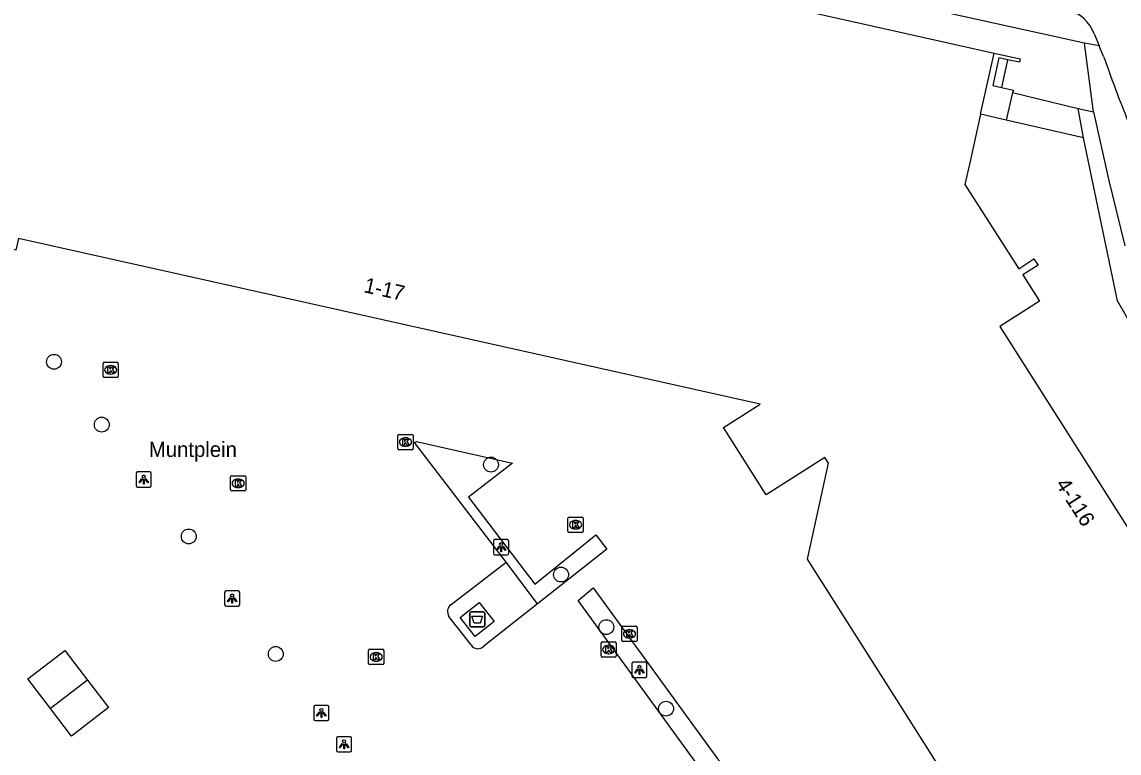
# Model space of a CAD drawing. Extents: x 161771 to 163125, y 382479 to 383177.
# Drawn here: x 162172.1 to 162244.3, y 382996.5 to 383044.7 of the extents above; entities that cross this region are included whole.
import ezdxf

# ---------------------------------------------------------------- set-up
doc = ezdxf.new("R2010")
doc.units = 0
for name, color, linetype in [('IMGEO_Afval_apart_plaats', 7, 'Continuous'), ('IMGEO_Boom', 7, 'Continuous'), ('IMGEO_Fietspad_gesloten', 7, 'Continuous'), ('IMGEO_Groenvoorziening', 7, 'Continuous'), ('IMGEO_Haag', 7, 'Continuous'), ('IMGEO_Kolk', 7, 'Continuous'), ('IMGEO_Lichtpunt', 7, 'Continuous'), ('IMGEO_Openbare_ruimte_label', 7, 'Continuous'), ('IMGEO_Pand', 7, 'Continuous'), ('IMGEO_Pand_nummerreeks', 7, 'Continuous'), ('IMGEO_Voetpad_gesloten', 7, 'Continuous'), ('IMGEO_Voetpad_open', 7, 'Continuous')]:
    doc.layers.add(name, color=color, linetype=linetype)

msp = doc.modelspace()

# ---------------------------------------------------------------- linework, layer by layer
at = {"layer": 'IMGEO_Afval_apart_plaats'}
for p, q in [((162201.588, 383004.906), (162201.588, 383005.706)), ((162201.588, 383005.706), (162201.588, 383004.906)), ((162201.688, 383005.806), (162202.478, 383005.806)), ((162202.478, 383005.806), (162201.688, 383005.806)), ((162202.578, 383005.706), (162202.578, 383004.906)), ((162202.578, 383004.906), (162202.578, 383005.706)), ((162202.478, 383004.806), (162201.688, 383004.806)), ((162201.688, 383004.806), (162202.478, 383004.806))]:
    msp.add_line(p, q, dxfattribs=at)
msp.add_lwpolyline([(162201.731, 383005.52), (162202.435, 383005.52), (162202.286, 383005.05), (162201.88, 383005.05), (162201.731, 383005.52)], dxfattribs=at)
for centre, start, end in [((162201.688, 383005.706), 90, 180), ((162201.688, 383005.706), 90, 180), ((162202.478, 383005.706), 0, 90), ((162202.478, 383005.706), 360, 90), ((162201.688, 383004.906), 180, 270), ((162201.688, 383004.906), 180, 270), ((162202.478, 383004.906), 270, 0), ((162202.478, 383004.906), 270, 0)]:
    msp.add_arc(centre, 0.1, start, end, dxfattribs=at)
at = {"layer": 'IMGEO_Boom'}
for centre in [(162174.228, 383022.27), (162177.372, 383018.135), (162202.992, 383015.501), (162183.098, 383010.768), (162207.602, 383008.259), (162210.585, 383004.797), (162188.826, 383003.033), (162214.515, 382999.426)]:
    msp.add_circle(centre, 0.489, dxfattribs=at)
at = {"layer": 'IMGEO_Fietspad_gesloten'}
for points in [[(162242.707, 383043.825), (162243.022, 383043.077)], [(162243.314, 383042.384), (162243.022, 383043.077)]]:
    msp.add_lwpolyline(points, dxfattribs=at)
for centre, radius, start, end in [((162240.222, 383042.932), 2.641, 19.77497, 74.56102), ((162333.223, 383073.685), 95.202, 199.19524, 201.97208)]:
    msp.add_arc(centre, radius, start, end, dxfattribs=at)
at = {"layer": 'IMGEO_Groenvoorziening'}
msp.add_lwpolyline([(162259.402, 382999.848), (162259.315, 383000), (162244.219, 383026.291), (162241.992, 383037.016)], dxfattribs=at)
at = {"layer": 'IMGEO_Haag'}
for points in [[(162203.991, 383009.068), (162197.95, 383016.959), (162198.094, 383017.031), (162204.406, 383015.589), (162201.521, 383013.363), (162205.876, 383007.632), (162209.901, 383010.868), (162210.617, 383009.929), (162206.053, 383006.34)], [(162231.583, 382975.071), (162208.719, 383006.559), (162209.718, 383007.386), (162232.645, 382975.85)]]:
    msp.add_lwpolyline(points, dxfattribs=at)
at = {"layer": 'IMGEO_Kolk'}
for p, q in [((162177.456, 383021.311), (162177.456, 383022.163)), ((162177.531, 383022.237), (162178.383, 383022.237)), ((162177.944, 383022.017), (162177.969, 383022.017)), ((162178.457, 383022.163), (162178.457, 383021.311)), ((162178.383, 383021.237), (162177.531, 383021.237)), ((162177.967, 383021.457), (162177.942, 383021.457)), ((162196.86, 383016.557), (162196.86, 383017.409)), ((162196.935, 383017.483), (162197.787, 383017.483)), ((162197.348, 383017.263), (162197.373, 383017.263)), ((162197.861, 383017.409), (162197.861, 383016.557)), ((162197.371, 383016.703), (162197.346, 383016.703)), ((162197.787, 383016.483), (162196.935, 383016.483)), ((162185.852, 383013.839), (162185.852, 383014.691)), ((162185.927, 383014.765), (162186.779, 383014.765)), ((162186.34, 383014.545), (162186.365, 383014.545)), ((162186.853, 383014.691), (162186.853, 383013.839)), ((162186.779, 383013.765), (162185.927, 383013.765)), ((162186.363, 383013.985), (162186.338, 383013.985)), ((162208.058, 383011.113), (162208.058, 383011.965)), ((162208.133, 383012.039), (162208.985, 383012.039)), ((162208.546, 383011.819), (162208.571, 383011.819)), ((162209.059, 383011.965), (162209.059, 383011.113)), ((162208.985, 383011.039), (162208.133, 383011.039)), ((162208.569, 383011.259), (162208.544, 383011.259)), ((162211.604, 383003.927), (162211.604, 383004.779)), ((162211.679, 383004.853), (162212.531, 383004.853)), ((162212.092, 383004.633), (162212.117, 383004.633)), ((162212.605, 383004.779), (162212.605, 383003.927)), ((162210.236, 383002.898), (162210.236, 383003.75)), ((162210.311, 383003.824), (162211.163, 383003.824)), ((162210.724, 383003.604), (162210.749, 383003.604)), ((162211.237, 383003.75), (162211.237, 383002.898)), ((162212.531, 383003.853), (162211.679, 383003.853)), ((162212.115, 383004.073), (162212.09, 383004.073)), ((162194.93, 383002.41), (162194.93, 383003.262)), ((162195.005, 383003.336), (162195.857, 383003.336)), ((162195.418, 383003.116), (162195.443, 383003.116)), ((162195.931, 383003.262), (162195.931, 383002.41)), ((162211.163, 383002.824), (162210.311, 383002.824)), ((162210.747, 383003.044), (162210.722, 383003.044)), ((162195.857, 383002.336), (162195.005, 383002.336)), ((162195.441, 383002.556), (162195.416, 383002.556))]:
    msp.add_line(p, q, dxfattribs=at)
for points in [[(162177.456, 383021.311), (162177.456, 383022.163)], [(162177.531, 383022.237), (162178.383, 383022.237)], [(162177.777, 383021.937), (162177.9, 383021.937), (162177.9, 383021.786), (162178.03, 383021.937), (162178.194, 383021.937), (162178.048, 383021.786), (162178.201, 383021.537), (162178.049, 383021.537), (162177.964, 383021.701), (162177.9, 383021.634), (162177.9, 383021.537), (162177.777, 383021.537), (162177.777, 383021.937)], [(162178.457, 383022.163), (162178.457, 383021.311)], [(162178.383, 383021.237), (162177.531, 383021.237)], [(162196.86, 383016.557), (162196.86, 383017.409)], [(162196.935, 383017.483), (162197.787, 383017.483)], [(162197.861, 383017.409), (162197.861, 383016.557)], [(162197.181, 383017.183), (162197.304, 383017.183), (162197.304, 383017.032), (162197.434, 383017.183), (162197.598, 383017.183), (162197.452, 383017.032), (162197.605, 383016.783), (162197.453, 383016.783), (162197.368, 383016.947), (162197.304, 383016.88), (162197.304, 383016.783), (162197.181, 383016.783), (162197.181, 383017.183)], [(162197.787, 383016.483), (162196.935, 383016.483)], [(162185.852, 383013.839), (162185.852, 383014.691)], [(162185.927, 383014.765), (162186.779, 383014.765)], [(162186.173, 383014.465), (162186.296, 383014.465), (162186.296, 383014.314), (162186.426, 383014.465), (162186.59, 383014.465), (162186.444, 383014.314), (162186.597, 383014.065), (162186.445, 383014.065), (162186.36, 383014.229), (162186.296, 383014.162), (162186.296, 383014.065), (162186.173, 383014.065), (162186.173, 383014.465)], [(162186.853, 383014.691), (162186.853, 383013.839)], [(162186.779, 383013.765), (162185.927, 383013.765)], [(162208.058, 383011.113), (162208.058, 383011.965)], [(162208.133, 383012.039), (162208.985, 383012.039)], [(162208.379, 383011.739), (162208.502, 383011.739), (162208.502, 383011.588), (162208.632, 383011.739), (162208.796, 383011.739), (162208.65, 383011.588), (162208.803, 383011.339), (162208.651, 383011.339), (162208.566, 383011.503), (162208.502, 383011.436), (162208.502, 383011.339), (162208.379, 383011.339), (162208.379, 383011.739)], [(162209.059, 383011.965), (162209.059, 383011.113)], [(162208.985, 383011.039), (162208.133, 383011.039)], [(162211.604, 383003.927), (162211.604, 383004.779)], [(162211.679, 383004.853), (162212.531, 383004.853)], [(162211.925, 383004.553), (162212.048, 383004.553), (162212.048, 383004.402), (162212.178, 383004.553), (162212.342, 383004.553), (162212.196, 383004.402), (162212.349, 383004.153), (162212.197, 383004.153), (162212.112, 383004.317), (162212.048, 383004.25), (162212.048, 383004.153), (162211.925, 383004.153), (162211.925, 383004.553)], [(162212.605, 383004.779), (162212.605, 383003.927)], [(162210.236, 383002.898), (162210.236, 383003.75)], [(162210.311, 383003.824), (162211.163, 383003.824)], [(162210.557, 383003.524), (162210.68, 383003.524), (162210.68, 383003.373), (162210.81, 383003.524), (162210.974, 383003.524), (162210.828, 383003.373), (162210.981, 383003.124), (162210.829, 383003.124), (162210.744, 383003.288), (162210.68, 383003.221), (162210.68, 383003.124), (162210.557, 383003.124), (162210.557, 383003.524)], [(162211.237, 383003.75), (162211.237, 383002.898)], [(162212.531, 383003.853), (162211.679, 383003.853)], [(162194.93, 383002.41), (162194.93, 383003.262)], [(162195.005, 383003.336), (162195.857, 383003.336)], [(162195.251, 383003.036), (162195.374, 383003.036), (162195.374, 383002.885), (162195.504, 383003.036), (162195.668, 383003.036), (162195.522, 383002.885), (162195.675, 383002.636), (162195.523, 383002.636), (162195.438, 383002.8), (162195.374, 383002.733), (162195.374, 383002.636), (162195.251, 383002.636), (162195.251, 383003.036)], [(162195.931, 383003.262), (162195.931, 383002.41)], [(162211.163, 383002.824), (162210.311, 383002.824)], [(162195.857, 383002.336), (162195.005, 383002.336)]]:
    msp.add_lwpolyline(points, dxfattribs=at)
for centre, start, end in [((162177.533, 383022.161), 91.55205, 178.44795), ((162177.533, 383022.161), 91.55205, 178.44795), ((162178.381, 383022.161), 1.55205, 88.44795), ((162178.381, 383022.161), 1.55205, 88.44795), ((162177.533, 383021.313), 181.55205, 268.44795), ((162177.533, 383021.313), 181.55205, 268.44795), ((162178.381, 383021.313), 271.55205, 358.44795), ((162178.381, 383021.313), 271.55205, 358.44795), ((162196.937, 383017.407), 91.55205, 178.44795), ((162196.937, 383017.407), 91.55205, 178.44795), ((162197.785, 383017.407), 1.55205, 88.44795), ((162197.785, 383017.407), 1.55205, 88.44795), ((162196.937, 383016.559), 181.55205, 268.44795), ((162196.937, 383016.559), 181.55205, 268.44795), ((162197.785, 383016.559), 271.55205, 358.44795), ((162197.785, 383016.559), 271.55205, 358.44795), ((162185.929, 383014.689), 91.55205, 178.44795), ((162185.929, 383014.689), 91.55205, 178.44795), ((162186.777, 383014.689), 1.55205, 88.44795), ((162186.777, 383014.689), 1.55205, 88.44795), ((162185.929, 383013.841), 181.55205, 268.44795), ((162185.929, 383013.841), 181.55205, 268.44795), ((162186.777, 383013.841), 271.55205, 358.44795), ((162186.777, 383013.841), 271.55205, 358.44795), ((162208.135, 383011.963), 91.55205, 178.44795), ((162208.135, 383011.963), 91.55205, 178.44795), ((162208.983, 383011.963), 1.55205, 88.44795), ((162208.983, 383011.963), 1.55205, 88.44795), ((162208.135, 383011.115), 181.55205, 268.44795), ((162208.135, 383011.115), 181.55205, 268.44795), ((162208.983, 383011.115), 271.55205, 358.44795), ((162208.983, 383011.115), 271.55205, 358.44795), ((162211.681, 383004.777), 91.55205, 178.44795), ((162211.681, 383004.777), 91.55205, 178.44795), ((162212.529, 383004.777), 1.55205, 88.44795), ((162212.529, 383004.777), 1.55205, 88.44795), ((162210.313, 383003.748), 91.55205, 178.44795), ((162210.313, 383003.748), 91.55205, 178.44795), ((162211.161, 383003.748), 1.55205, 88.44795), ((162211.161, 383003.748), 1.55205, 88.44795), ((162211.681, 383003.929), 181.55205, 268.44795), ((162211.681, 383003.929), 181.55205, 268.44795), ((162212.529, 383003.929), 271.55205, 358.44795), ((162212.529, 383003.929), 271.55205, 358.44795), ((162195.007, 383003.26), 91.55205, 178.44795), ((162195.007, 383003.26), 91.55205, 178.44795), ((162195.855, 383003.26), 1.55205, 88.44795), ((162195.855, 383003.26), 1.55205, 88.44795), ((162210.313, 383002.9), 181.55205, 268.44795), ((162210.313, 383002.9), 181.55205, 268.44795), ((162211.161, 383002.9), 271.55205, 358.44795), ((162211.161, 383002.9), 271.55205, 358.44795), ((162195.007, 383002.412), 181.55205, 268.44795), ((162195.007, 383002.412), 181.55205, 268.44795), ((162195.855, 383002.412), 271.55205, 358.44795), ((162195.855, 383002.412), 271.55205, 358.44795)]:
    msp.add_arc(centre, 0.0765, start, end, dxfattribs=at)
for centre, major_axis, ratio, start_param, end_param in [((162177.943, 383021.737), (-0.387, 0.002), 0.722429, 4.712389, 7.853982), ((162177.968, 383021.737), (-0.39, 0.002), 0.717154, 1.570796, 4.712389), ((162197.347, 383016.983), (-0.387, 0.002), 0.722429, 4.712389, 7.853982), ((162197.372, 383016.983), (-0.39, 0.002), 0.717154, 1.570796, 4.712389), ((162186.339, 383014.265), (-0.387, 0.002), 0.722429, 4.712389, 7.853982), ((162186.364, 383014.265), (-0.39, 0.002), 0.717154, 1.570796, 4.712389), ((162208.545, 383011.539), (-0.387, 0.002), 0.722429, 4.712389, 7.853982), ((162208.57, 383011.539), (-0.39, 0.002), 0.717154, 1.570796, 4.712389), ((162212.091, 383004.353), (-0.387, 0.002), 0.722429, 4.712389, 7.853982), ((162212.116, 383004.353), (-0.39, 0.002), 0.717154, 1.570796, 4.712389), ((162210.723, 383003.324), (-0.387, 0.002), 0.722429, 4.712389, 7.853982), ((162210.748, 383003.324), (-0.39, 0.002), 0.717154, 1.570796, 4.712389), ((162195.417, 383002.836), (-0.387, 0.002), 0.722429, 4.712389, 7.853982), ((162195.442, 383002.836), (-0.39, 0.002), 0.717154, 1.570796, 4.712389)]:
    msp.add_ellipse(centre, major_axis=major_axis, ratio=ratio, start_param=start_param, end_param=end_param, dxfattribs=at)
at = {"layer": 'IMGEO_Lichtpunt'}
for p, q in [((162179.637, 383014.923), (162179.637, 383014.116)), ((162179.637, 383014.923), (162179.637, 383014.116)), ((162180.539, 383015.018), (162179.731, 383015.018)), ((162180.539, 383015.018), (162179.731, 383015.018)), ((162180.633, 383014.116), (162180.633, 383014.923)), ((162180.633, 383014.116), (162180.633, 383014.923)), ((162179.731, 383014.022), (162180.539, 383014.022)), ((162179.731, 383014.022), (162180.539, 383014.022)), ((162203.158, 383010.464), (162203.158, 383009.657)), ((162203.158, 383010.464), (162203.158, 383009.657)), ((162204.06, 383010.559), (162203.252, 383010.559)), ((162204.06, 383010.559), (162203.252, 383010.559)), ((162204.154, 383009.657), (162204.154, 383010.464)), ((162204.154, 383009.657), (162204.154, 383010.464)), ((162203.252, 383009.563), (162204.06, 383009.563)), ((162203.252, 383009.563), (162204.06, 383009.563)), ((162186.358, 383007.18), (162185.55, 383007.18)), ((162186.358, 383007.18), (162185.55, 383007.18)), ((162185.456, 383007.085), (162185.456, 383006.278)), ((162185.456, 383007.085), (162185.456, 383006.278)), ((162186.452, 383006.278), (162186.452, 383007.085)), ((162186.452, 383006.278), (162186.452, 383007.085)), ((162185.55, 383006.184), (162186.358, 383006.184)), ((162185.55, 383006.184), (162186.358, 383006.184)), ((162212.262, 383002.388), (162212.262, 383001.581)), ((162212.262, 383002.388), (162212.262, 383001.581)), ((162213.164, 383002.483), (162212.356, 383002.483)), ((162213.164, 383002.483), (162212.356, 383002.483)), ((162213.258, 383001.581), (162213.258, 383002.388)), ((162213.258, 383001.581), (162213.258, 383002.388)), ((162212.356, 383001.487), (162213.164, 383001.487)), ((162212.356, 383001.487), (162213.164, 383001.487)), ((162191.327, 382999.552), (162191.327, 382998.745)), ((162191.327, 382999.552), (162191.327, 382998.745)), ((162192.229, 382999.647), (162191.421, 382999.647)), ((162192.229, 382999.647), (162191.421, 382999.647)), ((162192.323, 382998.745), (162192.323, 382999.552)), ((162192.323, 382998.745), (162192.323, 382999.552)), ((162191.421, 382998.651), (162192.229, 382998.651)), ((162191.421, 382998.651), (162192.229, 382998.651)), ((162192.824, 382997.48), (162192.824, 382996.673)), ((162192.824, 382997.48), (162192.824, 382996.673)), ((162193.726, 382997.575), (162192.918, 382997.575)), ((162193.726, 382997.575), (162192.918, 382997.575)), ((162193.82, 382996.673), (162193.82, 382997.48)), ((162193.82, 382996.673), (162193.82, 382997.48)), ((162192.918, 382996.579), (162193.726, 382996.579)), ((162192.918, 382996.579), (162193.726, 382996.579))]:
    msp.add_line(p, q, dxfattribs=at)
for points in [[(162180.011, 383014.587), (162180.05, 383014.559), (162179.862, 383014.297), (162179.824, 383014.324), (162180.011, 383014.587)], [(162180.113, 383014.539), (162180.16, 383014.539), (162180.16, 383014.217), (162180.113, 383014.217), (162180.113, 383014.539)], [(162180.223, 383014.559), (162180.261, 383014.586), (162180.448, 383014.324), (162180.409, 383014.296), (162180.223, 383014.559)], [(162203.532, 383010.128), (162203.571, 383010.1), (162203.383, 383009.838), (162203.345, 383009.865), (162203.532, 383010.128)], [(162203.634, 383010.08), (162203.681, 383010.08), (162203.681, 383009.758), (162203.634, 383009.758), (162203.634, 383010.08)], [(162203.744, 383010.1), (162203.782, 383010.127), (162203.969, 383009.865), (162203.93, 383009.837), (162203.744, 383010.1)], [(162185.83, 383006.749), (162185.869, 383006.721), (162185.681, 383006.459), (162185.643, 383006.486), (162185.83, 383006.749)], [(162185.932, 383006.701), (162185.979, 383006.701), (162185.979, 383006.379), (162185.932, 383006.379), (162185.932, 383006.701)], [(162186.042, 383006.721), (162186.08, 383006.748), (162186.267, 383006.486), (162186.228, 383006.458), (162186.042, 383006.721)], [(162212.636, 383002.052), (162212.675, 383002.024), (162212.487, 383001.762), (162212.449, 383001.789), (162212.636, 383002.052)], [(162212.738, 383002.004), (162212.785, 383002.004), (162212.785, 383001.682), (162212.738, 383001.682), (162212.738, 383002.004)], [(162212.848, 383002.024), (162212.886, 383002.051), (162213.073, 383001.789), (162213.034, 383001.761), (162212.848, 383002.024)], [(162191.701, 382999.216), (162191.74, 382999.188), (162191.552, 382998.926), (162191.514, 382998.953), (162191.701, 382999.216)], [(162191.913, 382999.188), (162191.951, 382999.215), (162192.138, 382998.953), (162192.099, 382998.925), (162191.913, 382999.188)], [(162191.803, 382999.168), (162191.85, 382999.168), (162191.85, 382998.846), (162191.803, 382998.846), (162191.803, 382999.168)], [(162193.198, 382997.144), (162193.237, 382997.116), (162193.049, 382996.854), (162193.011, 382996.881), (162193.198, 382997.144)], [(162193.3, 382997.096), (162193.347, 382997.096), (162193.347, 382996.774), (162193.3, 382996.774), (162193.3, 382997.096)], [(162193.41, 382997.116), (162193.448, 382997.143), (162193.635, 382996.881), (162193.596, 382996.853), (162193.41, 382997.116)]]:
    msp.add_lwpolyline(points, dxfattribs=at)
for centre in [(162180.136, 383014.721), (162203.657, 383010.262), (162185.955, 383006.883), (162212.761, 383002.186), (162191.826, 382999.35), (162193.323, 382997.278)]:
    msp.add_circle(centre, 0.0994, dxfattribs=at)
for centre, start, end in [((162179.731, 383014.923), 90, 180), ((162179.731, 383014.923), 90, 180), ((162180.539, 383014.923), 0, 90), ((162180.539, 383014.923), 0, 90), ((162179.731, 383014.116), 180, 270), ((162179.731, 383014.116), 180, 270), ((162180.539, 383014.116), 270, 0), ((162180.539, 383014.116), 270, 360), ((162203.252, 383010.464), 90, 180), ((162203.252, 383010.464), 90, 180), ((162204.06, 383010.464), 0, 90), ((162204.06, 383010.464), 0, 90), ((162203.252, 383009.657), 180, 270), ((162203.252, 383009.657), 180, 270), ((162204.06, 383009.657), 270, 0), ((162204.06, 383009.657), 270, 360), ((162185.55, 383007.085), 90, 180), ((162185.55, 383007.085), 90, 180), ((162186.358, 383007.085), 0, 90), ((162186.358, 383007.085), 0, 90), ((162185.55, 383006.278), 180, 270), ((162185.55, 383006.278), 180, 270), ((162186.358, 383006.278), 270, 0), ((162186.358, 383006.278), 270, 360), ((162212.356, 383002.388), 90, 180), ((162212.356, 383002.388), 90, 180), ((162213.164, 383002.388), 0, 90), ((162213.164, 383002.388), 0, 90), ((162212.356, 383001.581), 180, 270), ((162212.356, 383001.581), 180, 270), ((162213.164, 383001.581), 270, 0), ((162213.164, 383001.581), 270, 360), ((162191.421, 382999.552), 90, 180), ((162191.421, 382999.552), 90, 180), ((162192.229, 382999.552), 0, 90), ((162192.229, 382999.552), 0, 90), ((162191.421, 382998.745), 180, 270), ((162191.421, 382998.745), 180, 270), ((162192.229, 382998.745), 270, 0), ((162192.229, 382998.745), 270, 360), ((162192.918, 382997.48), 90, 180), ((162192.918, 382997.48), 90, 180), ((162193.726, 382997.48), 0, 90), ((162193.726, 382997.48), 0, 90), ((162192.918, 382996.673), 180, 270), ((162192.918, 382996.673), 180, 270), ((162193.726, 382996.673), 270, 0), ((162193.726, 382996.673), 270, 360)]:
    msp.add_arc(centre, 0.0946, start, end, dxfattribs=at)
at = {"layer": 'IMGEO_Pand'}
for points in [[(162177.897, 383057.502), (162177.562, 383055.68), (162228.166, 383044.363), (162236.101, 383042.589)], [(162235.21, 383038.577), (162236.101, 383042.589)], [(162235.21, 383038.577), (162234.544, 383035.577), (162234.18, 383033.937), (162237.732, 383028.397), (162238.726, 383029.045), (162238.997, 383028.624), (162237.993, 383027.987), (162239.092, 383026.259), (162236.485, 383024.601), (162252.111, 383000), (162254.878, 382995.644)], [(162234.295, 382992.755), (162229.703, 383000), (162223.821, 383009.282), (162225.198, 383015.586), (162224.97, 383015.963), (162221.106, 383013.505), (162218.291, 383017.954), (162220.699, 383019.481), (162171.9, 383030.395), (162171.715, 383029.631), (162151.435, 383034.151)], [(162173.99, 382999.441), (162172.501, 383001.385), (162174.944, 383003.255), (162176.431, 383001.313)], [(162176.431, 383001.313), (162177.821, 382999.497), (162175.378, 382997.627), (162173.99, 382999.441)], [(162176.431, 383001.313), (162173.99, 382999.441)]]:
    msp.add_lwpolyline(points, dxfattribs=at)
at = {"layer": 'IMGEO_Voetpad_gesloten'}
msp.add_lwpolyline([(162201.947, 383004.182), (162200.959, 383005.439), (162202.219, 383006.429), (162203.207, 383005.172), (162201.947, 383004.182)], dxfattribs=at)
at = {"layer": 'IMGEO_Voetpad_open'}
for points in [[(162242.054, 383043.244), (162238.25, 383044.089), (162228.586, 383046.238), (162177.897, 383057.502)], [(162242.642, 383038.727), (162242.054, 383043.244)], [(162243.022, 383043.077), (162242.054, 383043.244)], [(162236.101, 383042.589), (162237.83, 383042.213), (162237.78, 383042.005), (162236.984, 383042.163)], [(162236.984, 383042.163), (162236.412, 383042.288), (162236.013, 383040.458), (162236.591, 383040.341)], [(162236.984, 383042.163), (162236.591, 383040.341)], [(162236.591, 383040.341), (162237.378, 383040.163), (162237.314, 383040.008)], [(162237.314, 383040.008), (162236.909, 383038.191)], [(162237.314, 383040.008), (162241.63, 383038.949)], [(162241.63, 383038.949), (162242.642, 383038.727)], [(162241.992, 383037.016), (162241.63, 383038.949)], [(162236.909, 383038.191), (162235.21, 383038.577)], [(162241.992, 383037.016), (162236.909, 383038.191)], [(162242.642, 383038.727), (162243.636, 383034.288), (162244.714, 383029.905)], [(162200.374, 383006.286), (162203.991, 383009.068)], [(162206.053, 383006.34), (162203.991, 383009.068)], [(162206.053, 383006.34), (162202.51, 383003.538)], [(162201.682, 383003.625), (162200.225, 383005.507)]]:
    msp.add_lwpolyline(points, dxfattribs=at)
for centre, radius, start, end in [((162200.682, 383005.823), 0.555, 123.61897, 214.72457), ((162202.13, 383003.901), 0.526, 211.65816, 316.34544)]:
    msp.add_arc(centre, radius, start, end, dxfattribs=at)

# ---------------------------------------------------------------- texts
at = {"layer": 'IMGEO_Openbare_ruimte_label'}
msp.add_text('Muntplein', height=1, dxfattribs=at).set_placement((162180.471, 383016.003))
at = {"layer": 'IMGEO_Pand_nummerreeks'}
for s, rotation, p in [('1-17', 347.39314, (162194.566, 383026.863)), ('4-116', 302.42279, (162240.121, 383014.214))]:
    msp.add_text(s, height=1, rotation=rotation, dxfattribs=at).set_placement(p)

doc.saveas('drawing.dxf')
